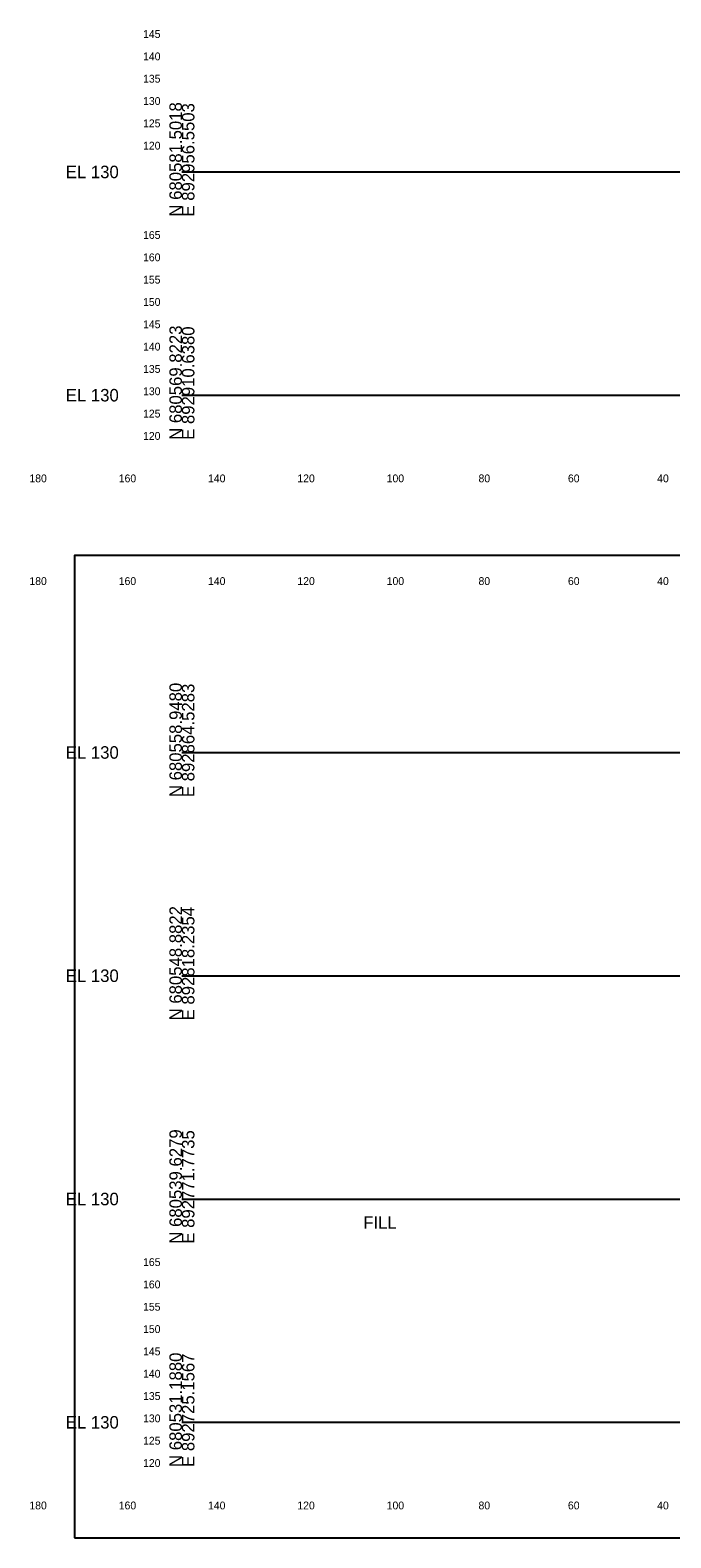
# Model space of a CAD drawing. Extents: x 21059 to 22955, y 6470 to 17494.
# Drawn here: x 21460.9 to 21604.3, y 7159 to 7496.6 of the extents above; entities that cross this region are included whole.
import ezdxf

# ---------------------------------------------------------------- set-up
doc = ezdxf.new("R2010")
doc.units = 0
for name, color, linetype in [('Draft_XS_Grid', 7, 'Continuous'), ('Draft_XS_Text', 7, 'Continuous'), ('DTM CONTOURS_MAJOR', 7, 'Continuous'), ('DTM_TEMP_DROP', 7, 'Continuous')]:
    doc.layers.add(name, color=color, linetype=linetype)

msp = doc.modelspace()

# ---------------------------------------------------------------- linework, layer by layer
at = {"layer": 'DTM CONTOURS_MAJOR'}
for p, q in [((21494.84, 7464.84), (21644.84, 7464.84)), ((21494.84, 7414.84), (21644.84, 7414.84)), ((21494.84, 7334.84), (21644.84, 7334.84)), ((21494.84, 7284.84), (21644.84, 7284.84)), ((21494.84, 7234.84), (21644.84, 7234.84)), ((21494.84, 7184.84), (21644.84, 7184.84))]:
    msp.add_line(p, q, dxfattribs=at)
at = {"layer": 'DTM_TEMP_DROP'}
msp.add_lwpolyline([(21470.8, 7158.96), (21816.8, 7158.96), (21816.8, 7378.96), (21470.8, 7378.96)], close=True, dxfattribs=at)

# ---------------------------------------------------------------- texts
at = {"layer": 'Draft_XS_Grid'}
for s, p in [('  145  ', (21484.84, 7494.84)), ('  140  ', (21484.84, 7489.84)), ('  135  ', (21484.84, 7484.84)), ('  130  ', (21484.84, 7479.84)), ('  125  ', (21484.84, 7474.84)), ('  120  ', (21484.84, 7469.84)), ('  165  ', (21484.84, 7449.84)), ('  160  ', (21484.84, 7444.84)), ('  155  ', (21484.84, 7439.84)), ('  150  ', (21484.84, 7434.84)), ('  145  ', (21484.84, 7429.84)), ('  140  ', (21484.84, 7424.84)), ('  135  ', (21484.84, 7419.84)), ('  130  ', (21484.84, 7414.84)), ('  125  ', (21484.84, 7409.84)), ('  120  ', (21484.84, 7404.84)), ('  165  ', (21484.84, 7219.84)), ('  160  ', (21484.84, 7214.84)), ('  155  ', (21484.84, 7209.84)), ('  150  ', (21484.84, 7204.84)), ('  145  ', (21484.84, 7199.84)), ('  140  ', (21484.84, 7194.84)), ('  135  ', (21484.84, 7189.84)), ('  130  ', (21484.84, 7184.84)), ('  125  ', (21484.84, 7179.84)), ('  120  ', (21484.84, 7174.84))]:
    msp.add_text(s, height=1.75, dxfattribs=at).set_placement(p)
at = {"layer": 'Draft_XS_Text'}
for s, height, p in [('  180  ', 1.75, (21459.39, 7395.34)), ('  160  ', 1.75, (21479.4, 7395.34)), ('  140  ', 1.75, (21499.39, 7395.34)), ('  120  ', 1.75, (21519.39, 7395.34)), ('  100  ', 1.75, (21539.39, 7395.34)), ('  80  ', 1.75, (21559.95, 7395.34)), ('  60  ', 1.75, (21579.97, 7395.34)), ('  40  ', 1.75, (21599.95, 7395.34)), ('  180  ', 1.75, (21459.39, 7372.34)), ('  160  ', 1.75, (21479.4, 7372.34)), ('  140  ', 1.75, (21499.39, 7372.34)), ('  120  ', 1.75, (21519.39, 7372.34)), ('  100  ', 1.75, (21539.39, 7372.34)), ('  80  ', 1.75, (21559.95, 7372.34)), ('  60  ', 1.75, (21579.97, 7372.34)), ('  40  ', 1.75, (21599.95, 7372.34)), ('FILL', 2.801, (21535.44, 7228.19)), ('  180  ', 1.75, (21459.39, 7165.34)), ('  160  ', 1.75, (21479.4, 7165.34)), ('  140  ', 1.75, (21499.39, 7165.34)), ('  120  ', 1.75, (21519.39, 7165.34)), ('  100  ', 1.75, (21539.39, 7165.34)), ('  80  ', 1.75, (21559.95, 7165.34)), ('  60  ', 1.75, (21579.97, 7165.34)), ('  40  ', 1.75, (21599.95, 7165.34))]:
    msp.add_text(s, height=height, dxfattribs=at).set_placement(p)
at = {"layer": 'DTM CONTOURS_MAJOR'}
for s, p in [('N 680581.5018', (21494.84, 7454.84)), ('E 892956.5503', (21497.64, 7454.84)), ('N 680569.8223', (21494.84, 7404.84)), ('E 892910.6380', (21497.64, 7404.84)), ('N 680558.9480', (21494.84, 7324.84)), ('E 892864.5283', (21497.64, 7324.84)), ('N 680548.8822', (21494.84, 7274.84)), ('E 892818.2354', (21497.64, 7274.84)), ('N 680539.6279', (21494.84, 7224.84)), ('E 892771.7735', (21497.64, 7224.84)), ('N 680531.1880', (21494.84, 7174.84)), ('E 892725.1567', (21497.64, 7174.84))]:
    msp.add_text(s, height=2.8, rotation=90, dxfattribs=at).set_placement(p)
for p in [(21468.84, 7463.44), (21468.84, 7413.44), (21468.84, 7333.44), (21468.84, 7283.44), (21468.84, 7233.44), (21468.84, 7183.44)]:
    msp.add_text('EL 130', height=2.8, dxfattribs=at).set_placement(p)

doc.saveas('drawing.dxf')
